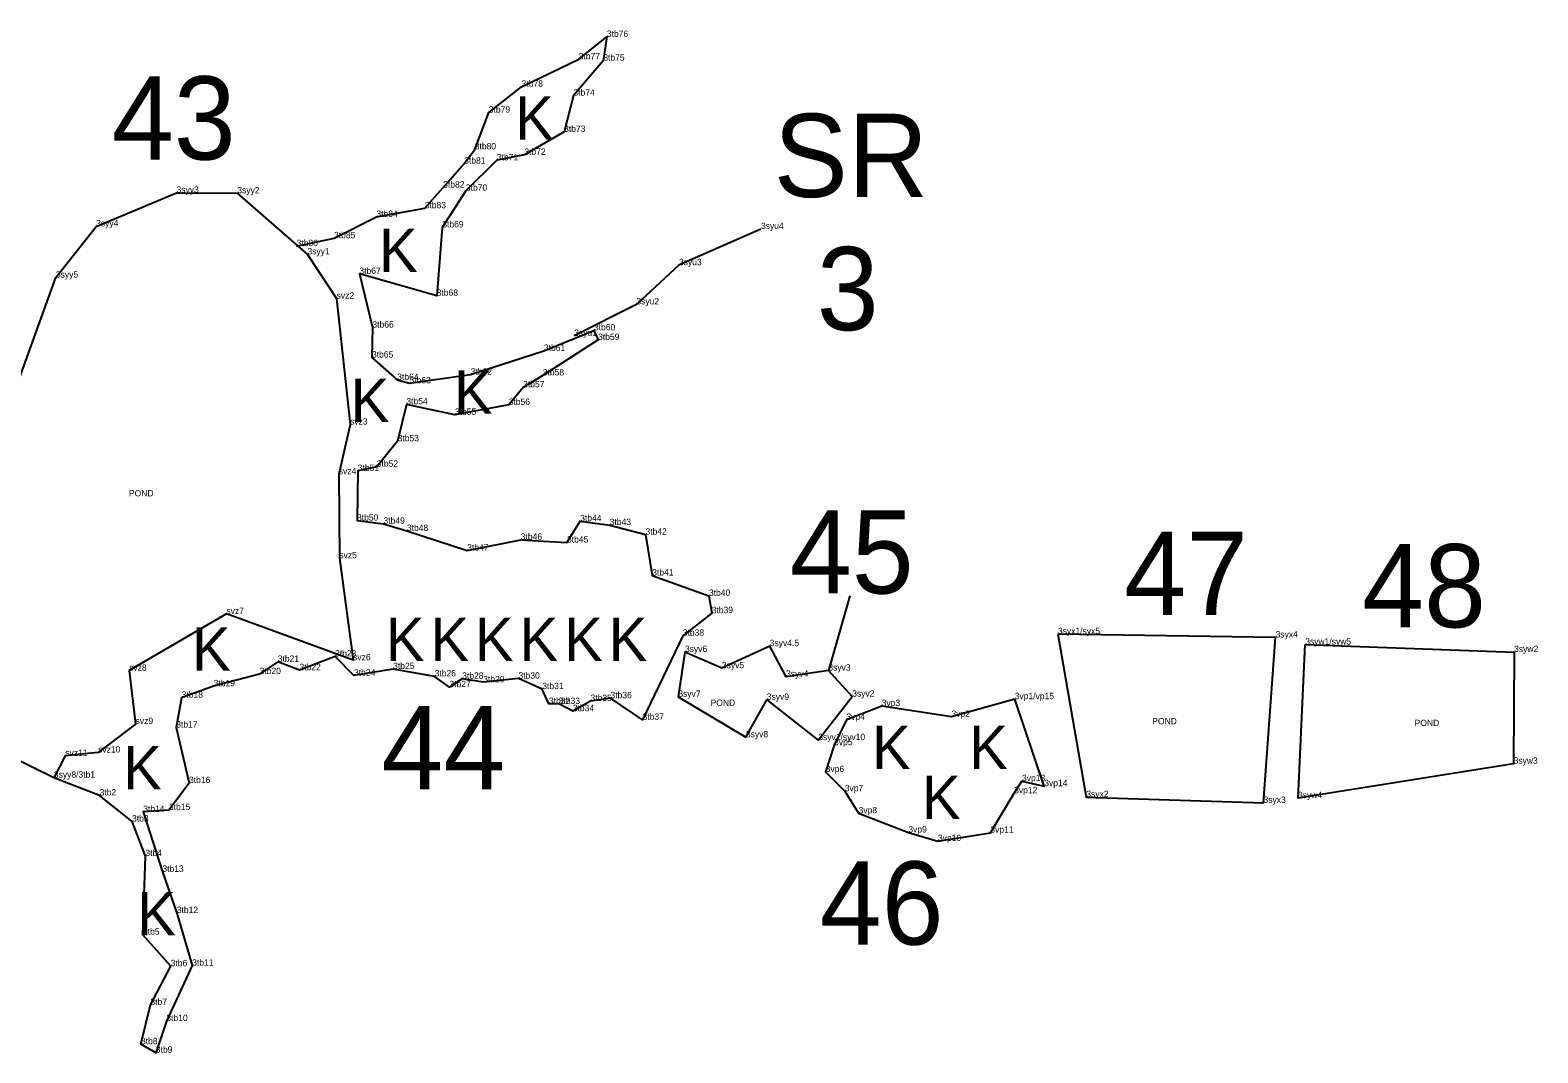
# Model space of a CAD drawing. Extents: x 2072529 to 2268812, y 436423 to 470008.
# Drawn here: x 2108603 to 2109787, y 455209 to 456011 of the extents above; entities that cross this region are included whole.
import ezdxf

# ---------------------------------------------------------------- set-up
doc = ezdxf.new("R2010")
doc.units = 0
for name, color, linetype in [('Old_Level_10', 7, 'Continuous'), ('Old_Level_20', 7, 'Continuous'), ('Old_Level_52', 7, 'Continuous'), ('Old_Level_55', 7, 'Continuous'), ('Old_Level_60', 7, 'Continuous'), ('Old_Level_62', 7, 'Continuous')]:
    doc.layers.add(name, color=color, linetype=linetype)

msp = doc.modelspace()

# ---------------------------------------------------------------- linework, layer by layer
at = {"layer": 'Old_Level_10'}
for points in [[(2108623.154, 455817.072), (2108654.717, 455857.226), (2108717.88, 455883.687), (2108765.604, 455883.247), (2108820.668, 455835.262), (2108843.596, 455800.56), (2108854.167, 455701.73), (2108845.29, 455662.75), (2108845.75, 455596.783), (2108856.574, 455516.675), (2108757.059, 455553.02), (2108680.693, 455508.553), (2108685.736, 455466.671), (2108656.308, 455444.288), (2108630.562, 455441.611), (2108621.566, 455424.538), (2108567.184, 455450.989), (2108505.196, 455491.556)], [(2109221.818, 455454.021), (2109248.477, 455488.174), (2109229.739, 455508.596), (2109196.568, 455503.741), (2109183.681, 455527.78), (2109146.136, 455510.422), (2109117.138, 455523.186), (2109111.894, 455487.978), (2109164.973, 455456.211), (2109181.362, 455485.651)], [(2109409.985, 455537.251), (2109432.251, 455409.299), (2109571.47, 455404.725), (2109580.919, 455534.576)], [(2109604.173, 455528.997), (2109768.246, 455523.154), (2109767.828, 455435.513), (2109598.533, 455408.478)]]:
    msp.add_lwpolyline(points, close=True, dxfattribs=at)
msp.add_lwpolyline([(2109176.788, 455855.191), (2109112.398, 455826.799), (2109079.011, 455796.056), (2109030.127, 455771.315)], dxfattribs=at)
at = {"layer": 'Old_Level_20'}
for p, q in [((2109055.811, 456006.029), (2109055.811, 456006.029)), ((2109033.68, 455988.411), (2109033.68, 455988.411)), ((2109053.005, 455987.337), (2109053.005, 455987.337)), ((2108988.886, 455966.915), (2108988.886, 455966.915)), ((2109029.558, 455959.939), (2109029.558, 455959.939)), ((2108963.089, 455946.569), (2108963.089, 455946.569)), ((2109022.22, 455931.414), (2109022.22, 455931.414)), ((2108952.076, 455917.711), (2108952.076, 455917.711)), ((2108943.753, 455906.554), (2108943.753, 455906.554)), ((2108969.423, 455909.133), (2108969.423, 455909.133)), ((2108991.02, 455913.433), (2108991.02, 455913.433)), ((2108717.88, 455883.687), (2108717.88, 455883.687)), ((2108765.604, 455883.247), (2108765.604, 455883.247)), ((2108927.269, 455887.699), (2108927.269, 455887.699)), ((2108945.07, 455885.226), (2108945.07, 455885.226)), ((2108912.756, 455871.487), (2108912.756, 455871.487)), ((2108654.717, 455857.226), (2108654.717, 455857.226)), ((2108874.83, 455864.72), (2108874.83, 455864.72)), ((2108841.549, 455847.951), (2108841.549, 455847.951)), ((2108926.57, 455856.453), (2108926.57, 455856.453)), ((2109176.788, 455855.191), (2109176.788, 455855.191)), ((2108812.176, 455841.762), (2108812.176, 455841.762)), ((2108820.668, 455835.262), (2108820.668, 455835.262)), ((2109112.398, 455826.799), (2109112.398, 455826.799)), ((2108623.154, 455817.072), (2108623.154, 455817.072)), ((2108861.482, 455819.971), (2108861.482, 455819.971)), ((2108843.596, 455800.56), (2108843.596, 455800.56)), ((2108922.156, 455802.792), (2108922.156, 455802.792)), ((2109079.011, 455796.056), (2109079.011, 455796.056)), ((2108871.703, 455777.84), (2108871.703, 455777.84)), ((2109045.643, 455775.634), (2109045.643, 455775.634)), ((2109030.127, 455771.315), (2109030.127, 455771.315)), ((2109048.914, 455768.138), (2109048.914, 455768.138)), ((2108871.361, 455754.311), (2108871.361, 455754.311)), ((2109006.324, 455759.567), (2109006.324, 455759.567)), ((2108948.809, 455740.96), (2108948.809, 455740.96)), ((2109005.465, 455740.297), (2109005.465, 455740.297)), ((2108891.191, 455736.744), (2108891.191, 455736.744)), ((2108900.836, 455734.085), (2108900.836, 455734.085)), ((2108990.055, 455730.898), (2108990.055, 455730.898)), ((2108898.346, 455717.578), (2108898.346, 455717.578)), ((2108978.707, 455717.125), (2108978.707, 455717.125)), ((2108936.467, 455709.329), (2108936.467, 455709.329)), ((2108854.167, 455701.73), (2108854.167, 455701.73)), ((2108891.518, 455688.589), (2108891.518, 455688.589)), ((2108875.099, 455668.598), (2108875.099, 455668.598)), ((2108845.29, 455662.75), (2108845.29, 455662.75)), ((2108860.233, 455665.28), (2108860.233, 455665.28)), ((2108859.62, 455626.349), (2108859.62, 455626.349)), ((2108880.399, 455623.887), (2108880.399, 455623.887)), ((2109034.865, 455625.825), (2109034.865, 455625.825)), ((2109058.049, 455622.847), (2109058.049, 455622.847)), ((2108898.786, 455618.212), (2108898.786, 455618.212)), ((2108988.218, 455611.283), (2108988.218, 455611.283)), ((2109024.477, 455609.107), (2109024.477, 455609.107)), ((2109086.125, 455615.352), (2109086.125, 455615.352)), ((2108845.75, 455596.783), (2108845.75, 455596.783)), ((2108946.186, 455602.801), (2108946.186, 455602.801)), ((2109091.403, 455583.22), (2109091.403, 455583.22)), ((2109135.951, 455567.244), (2109135.951, 455567.244)), ((2108757.059, 455553.02), (2108757.059, 455553.02)), ((2109138.124, 455553.679), (2109138.124, 455553.679)), ((2109115.443, 455535.951), (2109115.443, 455535.951)), ((2109183.681, 455527.78), (2109183.681, 455527.78)), ((2109409.985, 455537.251), (2109409.985, 455537.251)), ((2109580.919, 455534.576), (2109580.919, 455534.576)), ((2109604.173, 455528.997), (2109604.173, 455528.997)), ((2108797.366, 455515.452), (2108797.366, 455515.452)), ((2108842.38, 455519.673), (2108842.38, 455519.673)), ((2108856.574, 455516.675), (2108856.574, 455516.675)), ((2109117.138, 455523.186), (2109117.138, 455523.186)), ((2109768.246, 455523.154), (2109768.246, 455523.154)), ((2108680.693, 455508.553), (2108680.693, 455508.553)), ((2108783.107, 455505.871), (2108783.107, 455505.871)), ((2108814.454, 455508.911), (2108814.454, 455508.911)), ((2108857.227, 455504.643), (2108857.227, 455504.643)), ((2108887.975, 455509.805), (2108887.975, 455509.805)), ((2108920.558, 455504.043), (2108920.558, 455504.043)), ((2108942.219, 455502.132), (2108942.219, 455502.132)), ((2108986.416, 455502.27), (2108986.416, 455502.27)), ((2109146.136, 455510.422), (2109146.136, 455510.422)), ((2109196.568, 455503.741), (2109196.568, 455503.741)), ((2109229.739, 455508.596), (2109229.739, 455508.596)), ((2108747.025, 455496.297), (2108747.025, 455496.297)), ((2108932.162, 455495.601), (2108932.162, 455495.601)), ((2108958.697, 455499.428), (2108958.697, 455499.428)), ((2109005.099, 455494.062), (2109005.099, 455494.062)), ((2108721.901, 455487.27), (2108721.901, 455487.27)), ((2109010.277, 455482.387), (2109010.277, 455482.387)), ((2109017.968, 455482.425), (2109017.968, 455482.425)), ((2109042.976, 455484.696), (2109042.976, 455484.696)), ((2109058.624, 455486.899), (2109058.624, 455486.899)), ((2109111.894, 455487.978), (2109111.894, 455487.978)), ((2109181.362, 455485.651), (2109181.362, 455485.651)), ((2109248.477, 455488.174), (2109248.477, 455488.174)), ((2109271.624, 455480.799), (2109271.624, 455480.799)), ((2109376.098, 455486.152), (2109376.098, 455486.152)), ((2108685.736, 455466.671), (2108685.736, 455466.671)), ((2109029.032, 455476.739), (2109029.032, 455476.739)), ((2109083.819, 455469.986), (2109083.819, 455469.986)), ((2109243.923, 455469.931), (2109243.923, 455469.931)), ((2109326.402, 455472.25), (2109326.402, 455472.25)), ((2108717.621, 455463.881), (2108717.621, 455463.881)), ((2109164.973, 455456.211), (2109164.973, 455456.211)), ((2108656.308, 455444.288), (2108656.308, 455444.288)), ((2109221.818, 455454.021), (2109221.818, 455454.021)), ((2109234.245, 455450.053), (2109234.245, 455450.053)), ((2108630.562, 455441.611), (2108630.562, 455441.611)), ((2109767.828, 455435.513), (2109767.828, 455435.513)), ((2108621.566, 455424.538), (2108621.566, 455424.538)), ((2108621.566, 455424.538), (2108621.566, 455424.538)), ((2108727.696, 455420.295), (2108727.696, 455420.295)), ((2109227.606, 455429.014), (2109227.606, 455429.014)), ((2109381.779, 455421.85), (2109381.779, 455421.85)), ((2108657.443, 455410.558), (2108657.443, 455410.558)), ((2109242.597, 455413.874), (2109242.597, 455413.874)), ((2109375.629, 455412.348), (2109375.629, 455412.348)), ((2109399.269, 455417.872), (2109399.269, 455417.872)), ((2109432.251, 455409.299), (2109432.251, 455409.299)), ((2109598.533, 455408.478), (2109598.533, 455408.478)), ((2108691.721, 455397.649), (2108691.721, 455397.649)), ((2108711.966, 455399.097), (2108711.966, 455399.097)), ((2109253.499, 455396.561), (2109253.499, 455396.561)), ((2109571.47, 455404.725), (2109571.47, 455404.725)), ((2108682.951, 455390.113), (2108682.951, 455390.113)), ((2109292.539, 455381.524), (2109292.539, 455381.524)), ((2109315.789, 455374.788), (2109315.789, 455374.788)), ((2109356.972, 455381.344), (2109356.972, 455381.344)), ((2108693.441, 455363.001), (2108693.441, 455363.001)), ((2108706.776, 455350.635), (2108706.776, 455350.635)), ((2108718.071, 455318.27), (2108718.071, 455318.27)), ((2108691.542, 455301.28), (2108691.542, 455301.28)), ((2108730.2, 455277.014), (2108730.2, 455277.014)), ((2108713.292, 455276.558), (2108713.292, 455276.558)), ((2108697.377, 455246.134), (2108697.377, 455246.134)), ((2108709.894, 455233.494), (2108709.894, 455233.494)), ((2108689.982, 455215.353), (2108689.982, 455215.353)), ((2108701.63, 455208.631), (2108701.63, 455208.631))]:
    msp.add_line(p, q, dxfattribs=at)
at = {"layer": 'Old_Level_52'}
msp.add_lwpolyline([(2108812.176, 455841.762), (2108841.549, 455847.951), (2108874.83, 455864.72), (2108912.756, 455871.487), (2108927.269, 455887.699), (2108943.753, 455906.554), (2108952.076, 455917.711), (2108963.089, 455946.569), (2108988.886, 455966.915), (2109033.68, 455988.411), (2109055.811, 456006.029), (2109053.005, 455987.337), (2109029.558, 455959.939), (2109022.22, 455931.414), (2108991.02, 455913.433), (2108969.423, 455909.133), (2108945.07, 455885.226), (2108926.57, 455856.453), (2108922.156, 455802.792), (2108861.482, 455819.971), (2108871.703, 455777.84), (2108871.361, 455754.311), (2108891.191, 455736.744), (2108900.836, 455734.085), (2108948.809, 455740.96), (2109006.324, 455759.567), (2109045.643, 455775.634), (2109048.914, 455768.138), (2109005.465, 455740.297), (2108990.055, 455730.898), (2108978.707, 455717.125), (2108936.467, 455709.329), (2108898.346, 455717.578), (2108891.518, 455688.589), (2108875.099, 455668.598), (2108860.233, 455665.28), (2108859.62, 455626.349), (2108880.399, 455623.887), (2108898.786, 455618.212), (2108946.186, 455602.801), (2108988.218, 455611.283), (2109024.477, 455609.107), (2109034.865, 455625.825), (2109058.049, 455622.847), (2109086.125, 455615.352), (2109091.403, 455583.22), (2109135.951, 455567.244), (2109138.124, 455553.679), (2109115.443, 455535.951), (2109083.819, 455469.986), (2109058.624, 455486.899), (2109042.976, 455484.696), (2109029.032, 455476.739), (2109017.968, 455482.425), (2109010.277, 455482.387), (2109005.099, 455494.062), (2108986.416, 455502.27), (2108958.697, 455499.428), (2108942.219, 455502.132), (2108932.162, 455495.601), (2108920.558, 455504.043), (2108887.975, 455509.805), (2108857.227, 455504.643), (2108842.38, 455519.673), (2108814.454, 455508.911), (2108797.366, 455515.452), (2108783.107, 455505.871), (2108747.025, 455496.297), (2108721.901, 455487.27), (2108717.621, 455463.881), (2108727.696, 455420.295), (2108711.966, 455399.097), (2108691.721, 455397.649), (2108706.776, 455350.635), (2108718.071, 455318.27), (2108730.2, 455277.014), (2108709.894, 455233.494), (2108701.63, 455208.631), (2108689.982, 455215.353), (2108697.377, 455246.134), (2108713.292, 455276.558), (2108691.542, 455301.28), (2108693.441, 455363.001), (2108682.951, 455390.113), (2108657.443, 455410.558), (2108621.566, 455424.538)], dxfattribs=at)
msp.add_lwpolyline([(2109376.098, 455486.152), (2109326.402, 455472.25), (2109271.624, 455480.799), (2109243.923, 455469.931), (2109234.245, 455450.053), (2109227.606, 455429.014), (2109242.597, 455413.874), (2109253.499, 455396.561), (2109292.539, 455381.524), (2109315.789, 455374.788), (2109356.972, 455381.344), (2109375.629, 455412.348), (2109381.779, 455421.85), (2109399.269, 455417.872)], close=True, dxfattribs=at)
at = {"layer": 'Old_Level_62'}
msp.add_line((2109246.564, 455567.288), (2109229.739, 455508.596), dxfattribs=at)

# ---------------------------------------------------------------- texts
at = {"layer": 'Old_Level_55'}
for p in [(2108983.785, 455925.319), (2108876.937, 455821.52), (2108935.796, 455710.164), (2108854.665, 455703.8), (2108882.261, 455516.083), (2108917.261, 455516.083), (2108952.261, 455516.083), (2108987.261, 455516.083), (2109022.261, 455516.083), (2109057.261, 455516.083), (2108730.053, 455508.662), (2109264.032, 455431.243), (2109340.39, 455431.243), (2108675.965, 455415.335), (2109303.271, 455392.003), (2108687.101, 455300.797)]:
    msp.add_text('K', height=34, dxfattribs=at).set_placement(p)
at = {"layer": 'Old_Level_60'}
for s, p in [('3tb76', (2109055.811, 456006.029)), ('3tb77', (2109033.68, 455988.411)), ('3tb75', (2109053.005, 455987.337)), ('3tb78', (2108988.886, 455966.915)), ('3tb74', (2109029.558, 455959.939)), ('3tb79', (2108963.089, 455946.569)), ('3tb73', (2109022.22, 455931.414)), ('3tb80', (2108952.076, 455917.711)), ('3tb72', (2108991.02, 455913.433)), ('3tb81', (2108943.753, 455906.554)), ('3tb71', (2108969.423, 455909.133)), ('3tb82', (2108927.269, 455887.699)), ('3syy3', (2108717.88, 455883.687)), ('3syy2', (2108765.604, 455883.247)), ('3tb70', (2108945.07, 455885.226)), ('3tb84', (2108874.83, 455864.72)), ('3tb83', (2108912.756, 455871.487)), ('3syy4', (2108654.717, 455857.226)), ('3tb69', (2108926.57, 455856.453)), ('3syu4', (2109176.788, 455855.191)), ('3tb86', (2108812.176, 455841.762)), ('3tb85', (2108841.549, 455847.951)), ('3syy1', (2108820.668, 455835.262)), ('3syy5', (2108623.154, 455817.072)), ('3tb67', (2108861.482, 455819.971)), ('3syu3', (2109112.398, 455826.799)), ('svz2', (2108843.596, 455800.56)), ('3tb68', (2108922.156, 455802.792)), ('3syu2', (2109079.011, 455796.056)), ('3tb66', (2108871.703, 455777.84)), ('3syu1', (2109030.127, 455771.315)), ('3tb60', (2109045.643, 455775.634)), ('3tb61', (2109006.324, 455759.567)), ('3tb59', (2109048.914, 455768.138)), ('3tb65', (2108871.361, 455754.311)), ('3tb64', (2108891.191, 455736.744)), ('3tb63', (2108900.836, 455734.085)), ('3tb62', (2108948.809, 455740.96)), ('3tb58', (2109005.465, 455740.297)), ('3tb57', (2108990.055, 455730.898)), ('3tb54', (2108898.346, 455717.578)), ('3tb56', (2108978.707, 455717.125)), ('svz3', (2108854.167, 455701.73)), ('3tb55', (2108936.467, 455709.329)), ('3tb53', (2108891.518, 455688.589)), ('svz4', (2108845.29, 455662.75)), ('3tb51', (2108860.233, 455665.28)), ('3tb52', (2108875.099, 455668.598)), ('POND', (2108680.523, 455645.321)), ('3tb50', (2108859.62, 455626.349)), ('3tb49', (2108880.399, 455623.887)), ('3tb48', (2108898.786, 455618.212)), ('3tb44', (2109034.865, 455625.825)), ('3tb43', (2109058.049, 455622.847)), ('3tb42', (2109086.125, 455615.352)), ('3tb46', (2108988.218, 455611.283)), ('3tb45', (2109024.477, 455609.107)), ('svz5', (2108845.75, 455596.783)), ('3tb47', (2108946.186, 455602.801)), ('3tb41', (2109091.403, 455583.22)), ('3tb40', (2109135.951, 455567.244)), ('svz7', (2108757.059, 455553.02)), ('3tb39', (2109138.124, 455553.679)), ('3tb38', (2109115.443, 455535.951)), ('3syx1/syx5', (2109409.985, 455537.251)), ('3syx4', (2109580.919, 455534.576)), ('3syv6', (2109117.138, 455523.186)), ('3syv4.5', (2109183.681, 455527.78)), ('3syw1/syw5', (2109604.173, 455528.997)), ('3syw2', (2109768.246, 455523.154)), ('3tb21', (2108797.366, 455515.452)), ('3tb22', (2108814.454, 455508.911)), ('3tb23', (2108842.38, 455519.673)), ('svz6', (2108856.574, 455516.675)), ('3tb25', (2108887.975, 455509.805)), ('3syv5', (2109146.136, 455510.422)), ('svz8', (2108680.693, 455508.553)), ('3tb20', (2108783.107, 455505.871)), ('3tb24', (2108857.227, 455504.643)), ('3tb26', (2108920.558, 455504.043)), ('3tb28', (2108942.219, 455502.132)), ('3tb29', (2108958.697, 455499.428)), ('3tb30', (2108986.416, 455502.27)), ('3syv4', (2109196.568, 455503.741)), ('3syv3', (2109229.739, 455508.596)), ('3tb18', (2108721.901, 455487.27)), ('3tb19', (2108747.025, 455496.297)), ('3tb27', (2108932.162, 455495.601)), ('3tb31', (2109005.099, 455494.062)), ('3tb36', (2109058.624, 455486.899)), ('3syv7', (2109111.894, 455487.978)), ('3syv9', (2109181.362, 455485.651)), ('3syv2', (2109248.477, 455488.174)), ('3vp1/vp15', (2109376.098, 455486.152)), ('3tb32', (2109010.277, 455482.387)), ('3tb33', (2109017.968, 455482.425)), ('3tb34', (2109029.032, 455476.739)), ('3tb35', (2109042.976, 455484.696)), ('POND', (2109137.277, 455480.882)), ('3vp3', (2109271.624, 455480.799)), ('svz9', (2108685.736, 455466.671)), ('3tb17', (2108717.621, 455463.881)), ('3tb37', (2109083.819, 455469.986)), ('3vp4', (2109243.923, 455469.931)), ('3vp2', (2109326.402, 455472.25)), ('POND', (2109484.089, 455466.457)), ('POND', (2109690.133, 455465.015)), ('3syv8', (2109164.973, 455456.211)), ('3syv1/syv10', (2109221.818, 455454.021)), ('3vp5', (2109234.245, 455450.053)), ('svz11', (2108630.562, 455441.611)), ('svz10', (2108656.308, 455444.288)), ('3vp6', (2109227.606, 455429.014)), ('3syw3', (2109767.828, 455435.513)), ('3syy8/3tb1', (2108621.566, 455424.538)), ('3syy8/3tb1', (2108621.566, 455424.538)), ('3tb16', (2108727.696, 455420.295)), ('3vp13', (2109381.779, 455421.85)), ('3vp14', (2109399.269, 455417.872)), ('3tb2', (2108657.443, 455410.558)), ('3vp7', (2109242.597, 455413.874)), ('3vp12', (2109375.629, 455412.348)), ('3syx2', (2109432.251, 455409.299)), ('3syx3', (2109571.47, 455404.725)), ('3syw4', (2109598.533, 455408.478)), ('3tb14', (2108691.721, 455397.649)), ('3tb15', (2108711.966, 455399.097)), ('3vp8', (2109253.499, 455396.561)), ('3tb3', (2108682.951, 455390.113)), ('3vp9', (2109292.539, 455381.524)), ('3vp11', (2109356.972, 455381.344)), ('3vp10', (2109315.789, 455374.788)), ('3tb4', (2108693.441, 455363.001)), ('3tb13', (2108706.776, 455350.635)), ('3tb12', (2108718.071, 455318.27)), ('3tb5', (2108691.542, 455301.28)), ('3tb6', (2108713.292, 455276.558)), ('3tb11', (2108730.2, 455277.014)), ('3tb7', (2108697.377, 455246.134)), ('3tb10', (2108709.894, 455233.494)), ('3tb8', (2108689.982, 455215.353)), ('3tb9', (2108701.63, 455208.631))]:
    msp.add_text(s, height=5, dxfattribs=at).set_placement(p)
at = {"layer": 'Old_Level_62'}
for s, p in [('43', (2108667.164, 455909.682)), ('SR', (2109186.757, 455880.34)), ('3', (2109220.69, 455775.796)), ('45', (2109199.528, 455569.129)), ('47', (2109462.103, 455552.341)), ('48', (2109648.934, 455542.528)), ('44', (2108878.775, 455415.441)), ('46', (2109223.007, 455293.479))]:
    msp.add_text(s, height=65.34, dxfattribs=at).set_placement(p)

doc.saveas('drawing.dxf')
